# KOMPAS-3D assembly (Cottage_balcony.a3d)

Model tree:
1. Plane XY
2. Plane ZX
3. Plane ZY
4. X Axis
5. Y Axis
6. Z Axis
7. Origin
8. Offset Plane:1
     Distance = 320
9. Sketch:1
10. Cut-Extrude:1
     Wall Thickness 1 = 1; Wall Thickness 2 = 1; Distance 2 = 10; Distance 1 = 400
11. Sketch:2
12. Cut-Extrude:2
     Wall Thickness 1 = 1; Wall Thickness 2 = 1; Distance 2 = 10; Distance 1 = 400
13. Offset Plane:2
     Distance = 200
14. Sketch:3
15. Extruded Surface:2
     Wall Thickness 1 = 1; Wall Thickness 2 = 10; Distance 2 = 4000
16. Axis through Two Vertices:4
17. Axis through Two Vertices:5
18. Axis through Two Vertices:6
19. Axis through Two Vertices:7
20. Axis through Two Vertices:8
21. Linear Pattern:1  (labels: Instance ( 2, 1 );; Instance ( 1, 2 );; Instance ( 2, 2 );)
     N 1 = 2; Included Angle = 90; N 2 = 2
22. Linear Pattern:2  (labels: Instance ( 2, 1 );; Instance ( 1, 2 );; Instance ( 2, 2 );)
     N 1 = 2; Included Angle = 90; N 2 = 2; Orientation = 2; Orientation = 2; Orientation = 2; Orientation = 2; Orientation = 2; Orientation = 2; Orientation = 2; Orientation = 2; Orientation = 2; Distance = -10; Orientation = 1; Distance = -10; Orientation = 1; Orientation = 2; Orientation = 2; Orientation = 2; Orientation = 2; Distance = 29; Orientation = 1; Distance = 29; Orientation = 1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

Referenced files in D:\Documents and Settings\kashirsky\Рабочий стол\Seminar\: Foundation.m3d, Wall.m3d, Roof space.m3d, Roof.m3d, Floor.m3d, Plate1.m3d, Tube1.m3d, Profile1.m3d, Profile2.m3d, Plate2.m3d, Tube2.m3d, Profile3.m3d, Profile4.m3d, Tube3.m3d
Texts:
  Three Point Plane
  Plane at Angle
  Line and Point Plane
  Axis through Two Vertices
  Axis of Feature
  Axis of Conical Surface
  Axis through Edge
  Trim by Surface
  Trim by Sketch
  Intersection Axis of Two Planes
  Two Line Plane
  Line and Face Plane
  Pattern by Sample
  Point in CM
  Feature with No History
  Linear Dimension from Line to Point
  Surface Finish Symbol
  Geometric Tolerance Symbol
  Leader #1
  Leader #2
  Leader #3
  Shape Deviations and Datum
  Node point number
  Mark of coordination axis
  Node point designation
  Mark/Reference designation with leader
  Mark/reference designation on line
  Mark/Reference designation without leader
  Length1
  Length2
  Heigth1
  Heigth2
  Instance ( 2, 1 );
  Instance ( 1, 2 );
  Instance ( 2, 2 );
